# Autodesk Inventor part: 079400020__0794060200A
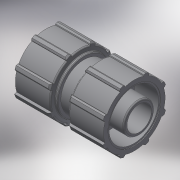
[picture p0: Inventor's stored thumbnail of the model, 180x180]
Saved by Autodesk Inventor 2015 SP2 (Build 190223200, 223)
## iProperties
Created: 2017-04
Part Number: 079400020__0794060200A
Material: Generic
Description: PLASSON MODULAR ADAPTOR 20
Document SubType Name: Modeling
Designer: KIM
Mass: 64.7584 g
Surface Area: 263.007 cm^2
Volume: 64.7584 cm^3
Density: 1 g/cm^3
Appearance: Default
Author: KIM
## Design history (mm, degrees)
derived "07940.ipt"
feature "Solid1::07940.ipt"
tag "TaggingFeature1"
body "Solid1"
other parameters: "d7" = 48, "d8" = 38.4, "d15" = 36, "d17" = 32, "d43" = 100 deg, "d46" = 44.64, "d47" = 35 deg, "d48" = 17.5 deg, "d50" = 0, "d52" = 360 deg, "d54" = 0.96, "d57" = 0.96, "d68" = 28.8, "d69" = 0.5, "d70" = 2.88, "d71" = 5, "d72" = 16, "d74" = 36, "d75" = 33.6, "d76" = 0.48, "d77" = 0.96, "d79" = 360 deg, "d81" = 0.96, "d82" = 16, "E_" = 48
